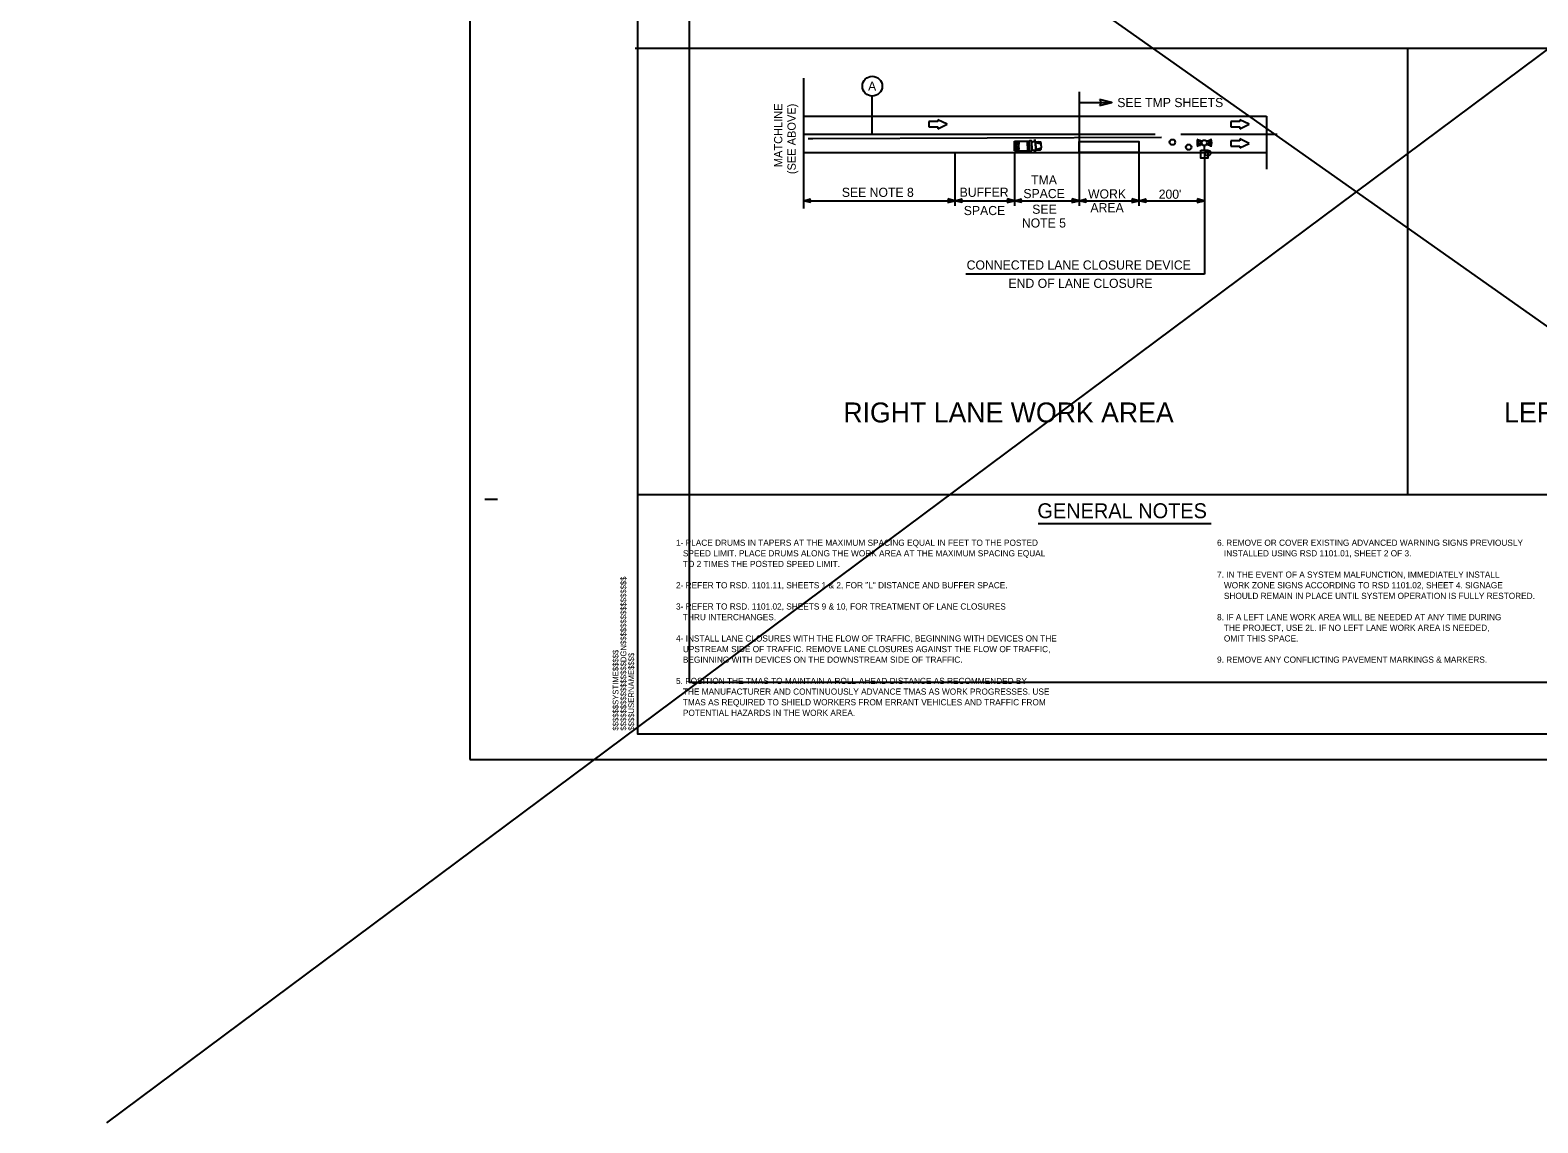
# Model space of a CAD drawing. Extents: x 1379436 to 1387057, y 792703 to 795604.
# Drawn here: x 1379436 to 1381631, y 792703 to 794294 of the extents above; entities that cross this region are included whole.
import ezdxf

# ---------------------------------------------------------------- set-up
doc = ezdxf.new("R2010")
doc.units = 0
for name, color, linetype in [('Default', 7, 'Continuous'), ('DEV BORDER CELL', 7, 'Continuous'), ('DEV DIRECTION OF TRAFFIC FLOW ARROW CELL', 7, 'Continuous'), ('DEV DRUM PLAN VIEW CELL', 7, 'Continuous'), ('DEV LINE TERMINATOR TYPE 3 CELL', 7, 'Continuous'), ('DEV TRUCK MOUNTED IMPACT ATTENUATOR CELL', 7, 'Continuous'), ('Drum Linestyle V8i', 7, 'Continuous'), ('Gray Area Fill Shapes', 7, 'Continuous'), ('Prop Mkg Skp Wht', 7, 'Continuous'), ('Prop Mkg Solid White Lane Line', 7, 'Continuous'), ('Prop Mkg Solid Yellow Edge Line', 7, 'Continuous'), ('Scratch_Level_0', 7, 'Continuous'), ('Sheet Plot Border Outside CELL', 7, 'Continuous'), ('Text', 7, 'Continuous')]:
    doc.layers.add(name, color=color, linetype=linetype)

msp = doc.modelspace()

# ---------------------------------------------------------------- linework, layer by layer
at = {"layer": 'Default'}
for p, q in [((1379547.9, 792703.3), (1383441.1, 795604.3)), ((1379436.3, 795421.7), (1382883.5, 792987.4)), ((1380317, 794267.8), (1382567, 794267.8)), ((1381442, 793618), (1381442, 794267.8)), ((1380662.3, 794142.3), (1380662.3, 794198)), ((1380963.2, 794204.2), (1380963.2, 794115.6)), ((1380320.7, 793618), (1381738.3, 793618))]:
    msp.add_line(p, q, dxfattribs=at)
msp.add_circle((1380662.3, 794212.4), 14.4, dxfattribs=at)
at = {"layer": 'DEV BORDER CELL'}
for p, q in [((1380098, 793611), (1380116.7, 793611)), ((1380320.7, 793269.7), (1380320.7, 793269.7))]:
    msp.add_line(p, q, dxfattribs=at)
msp.add_lwpolyline([(1382570.8, 794844.7), (1380320.7, 794844.7), (1380320.7, 793269.7), (1382570.8, 793269.7)], close=True, dxfattribs=at)
at = {"layer": 'DEV DIRECTION OF TRAFFIC FLOW ARROW CELL'}
for p, q in [((1380771.4, 794157), (1380757.6, 794163.5)), ((1380757.6, 794163.5), (1380757.6, 794160.9)), ((1381210.9, 794157), (1381197.2, 794163.5)), ((1381197.2, 794163.5), (1381197.2, 794160.9)), ((1380757.6, 794160.9), (1380744.8, 794160.9)), ((1380744.8, 794160.9), (1380744.8, 794153.2)), ((1380744.8, 794153.2), (1380757.6, 794153.2)), ((1380757.6, 794150.5), (1380771.4, 794157)), ((1380757.6, 794153.2), (1380757.6, 794150.5)), ((1381197.2, 794160.9), (1381184.4, 794160.9)), ((1381184.4, 794160.9), (1381184.4, 794153.2)), ((1381184.4, 794153.2), (1381197.2, 794153.2)), ((1381197.2, 794150.5), (1381210.9, 794157)), ((1381197.2, 794153.2), (1381197.2, 794150.5)), ((1381197.2, 794132.9), (1381184.4, 794132.9)), ((1381184.4, 794132.9), (1381184.4, 794125.2)), ((1381184.4, 794125.2), (1381197.2, 794125.2)), ((1381210.9, 794129.1), (1381197.2, 794135.5)), ((1381197.2, 794135.5), (1381197.2, 794132.9)), ((1381197.2, 794122.6), (1381210.9, 794129.1)), ((1381197.2, 794125.2), (1381197.2, 794122.6))]:
    msp.add_line(p, q, dxfattribs=at)
at = {"layer": 'DEV DRUM PLAN VIEW CELL'}
for centre in [(1381099.1, 794130.9), (1381099.1, 794130.9), (1381122.8, 794123.6), (1381122.8, 794123.6), (1381150.8, 794115.2), (1381150.8, 794115.2)]:
    msp.add_circle(centre, 4.08, dxfattribs=at)
at = {"layer": 'DEV LINE TERMINATOR TYPE 3 CELL'}
for points in [[(1380993.3, 794184.1), (1381011, 794188.6), (1380993.3, 794193)], [(1380993.3, 794184.1), (1381011, 794188.6), (1380993.3, 794193)], [(1380572.3, 794043), (1380561.9, 794045.6), (1380572.3, 794048.2)], [(1380572.3, 794043), (1380561.9, 794045.6), (1380572.3, 794048.2)], [(1380772.2, 794043), (1380782.6, 794045.6), (1380772.2, 794048.2)], [(1380772.2, 794043), (1380782.6, 794045.6), (1380772.2, 794048.2)], [(1380793, 794043), (1380782.6, 794045.6), (1380793, 794048.2)], [(1380793, 794043), (1380782.6, 794045.6), (1380793, 794048.2)], [(1380858.7, 794043), (1380869.1, 794045.6), (1380858.7, 794048.2)], [(1380858.7, 794043), (1380869.1, 794045.6), (1380858.7, 794048.2)], [(1380879.5, 794043), (1380869.1, 794045.6), (1380879.5, 794048.2)], [(1380879.5, 794043), (1380869.1, 794045.6), (1380879.5, 794048.2)], [(1380952.8, 794043), (1380963.2, 794045.6), (1380952.8, 794048.2)], [(1380952.8, 794043), (1380963.2, 794045.6), (1380952.8, 794048.2)], [(1380973.6, 794043), (1380963.2, 794045.6), (1380973.6, 794048.2)], [(1380973.6, 794043), (1380963.2, 794045.6), (1380973.6, 794048.2)], [(1381040.2, 794043), (1381050.5, 794045.6), (1381040.2, 794048.2)], [(1381040.2, 794043), (1381050.5, 794045.6), (1381040.2, 794048.2)], [(1381060.9, 794043), (1381050.5, 794045.6), (1381060.9, 794048.2)], [(1381060.9, 794043), (1381050.5, 794045.6), (1381060.9, 794048.2)], [(1381135.3, 794043), (1381145.6, 794045.6), (1381135.3, 794048.2)], [(1381135.3, 794043), (1381145.6, 794045.6), (1381135.3, 794048.2)]]:
    msp.add_lwpolyline(points, dxfattribs=at)
for centre, radius, start, end in [((1380989.4, 794188.6), 5.92, 311.3264, 48.6736), ((1380989.4, 794188.6), 5.92, 311.3264, 48.6736), ((1380574.6, 794045.6), 3.46, 131.3264, 228.6736), ((1380574.6, 794045.6), 3.46, 131.3264, 228.6736), ((1380769.9, 794045.6), 3.46, 311.3264, 48.6736), ((1380769.9, 794045.6), 3.46, 311.3264, 48.6736), ((1380795.2, 794045.6), 3.46, 131.3264, 228.6736), ((1380795.2, 794045.6), 3.46, 131.3264, 228.6736), ((1380856.5, 794045.6), 3.46, 311.3264, 48.6736), ((1380856.5, 794045.6), 3.46, 311.3264, 48.6736), ((1380881.8, 794045.6), 3.46, 131.3264, 228.6736), ((1380881.8, 794045.6), 3.46, 131.3264, 228.6736), ((1380950.5, 794045.6), 3.46, 311.3264, 48.6736), ((1380950.5, 794045.6), 3.46, 311.3264, 48.6736), ((1380975.8, 794045.6), 3.46, 131.3264, 228.6736), ((1380975.8, 794045.6), 3.46, 131.3264, 228.6736), ((1381037.9, 794045.6), 3.46, 311.3264, 48.6736), ((1381037.9, 794045.6), 3.46, 311.3264, 48.6736), ((1381063.2, 794045.6), 3.46, 131.3264, 228.6736), ((1381063.2, 794045.6), 3.46, 131.3264, 228.6736), ((1381133, 794045.6), 3.46, 311.3264, 48.6736), ((1381133, 794045.6), 3.46, 311.3264, 48.6736)]:
    msp.add_arc(centre, radius, start, end, dxfattribs=at)
at = {"layer": 'DEV TRUCK MOUNTED IMPACT ATTENUATOR CELL'}
for p, q in [((1380869.1, 794132.5), (1380891, 794132.5)), ((1380869.1, 794118.3), (1380869.1, 794132.5)), ((1380869.1, 794132.5), (1380869.1, 794129.8)), ((1380869.1, 794132.5), (1380869.1, 794129.8)), ((1380869.1, 794132.5), (1380869.1, 794129.8)), ((1380869.1, 794132.5), (1380869.1, 794129.8)), ((1380869.1, 794129.8), (1380869.1, 794132.5)), ((1380869.1, 794132.5), (1380871.5, 794132.5)), ((1380871.5, 794132.5), (1380869.1, 794129.8)), ((1380869.1, 794127.6), (1380873.5, 794132.5)), ((1380875.4, 794132.5), (1380869.1, 794125.4)), ((1380869.1, 794125.4), (1380869.1, 794127.6)), ((1380869.1, 794125.4), (1380875.4, 794118.3)), ((1380869.1, 794123.3), (1380869.1, 794125.4)), ((1380873.5, 794118.3), (1380869.1, 794123.3)), ((1380869.1, 794121), (1380869.1, 794118.3)), ((1380871.5, 794118.3), (1380869.1, 794121)), ((1380871.1, 794125.4), (1380875.4, 794130.3)), ((1380875.4, 794120.6), (1380871.1, 794125.4)), ((1380875.4, 794128.1), (1380873, 794125.4)), ((1380873.1, 794125.4), (1380875.4, 794122.8)), ((1380873.5, 794132.5), (1380875.4, 794132.5)), ((1380875.4, 794118.3), (1380875.4, 794132.5)), ((1380875.4, 794130.3), (1380875.4, 794128.1)), ((1380875.4, 794122.8), (1380875.4, 794120.6)), ((1380888, 794125.4), (1380888, 794132.5)), ((1380888, 794125.4), (1380888, 794118.3)), ((1380891, 794125.4), (1380891, 794132.5)), ((1380891, 794125.4), (1380891, 794118.3)), ((1380894.3, 794125.4), (1380894.3, 794132.5)), ((1380894.3, 794125.4), (1380894.3, 794118.3)), ((1380898.8, 794132.9), (1380898.8, 794134.6)), ((1380899.1, 794131.2), (1380899.1, 794134.6)), ((1380899.1, 794119.6), (1380899.1, 794116.2)), ((1380899.3, 794131.2), (1380899.3, 794134.6)), ((1380899.3, 794119.6), (1380899.3, 794116.2)), ((1380899.9, 794125.4), (1380899.9, 794130.5)), ((1380899.9, 794125.4), (1380899.9, 794120.3)), ((1380900.4, 794130.5), (1380908.1, 794128.4)), ((1380900.4, 794125.4), (1380900.4, 794130.5)), ((1380900.4, 794125.4), (1380900.4, 794120.3)), ((1380900.4, 794120.3), (1380908.1, 794122.4)), ((1380908.1, 794125.4), (1380908.1, 794128.4)), ((1380908.1, 794125.4), (1380908.1, 794122.4)), ((1380869.1, 794118.3), (1380891, 794118.3)), ((1380869.1, 794118.3), (1380871.5, 794118.3)), ((1380875.4, 794118.3), (1380873.5, 794118.3)), ((1380898.8, 794117.9), (1380898.8, 794116.2))]:
    msp.add_line(p, q, dxfattribs=at)
for centre in [(1380906.2, 794129.4), (1380906.2, 794121.4)]:
    msp.add_arc(centre, 2.12, 331.8801, 28.1199, dxfattribs=at)
for centre, major_axis, ratio, start_param, end_param in [((1380892.7, 794132.5), (1.67, 0), 0.269913, 0, 3.141593), ((1380897.1, 794130.1), (2.8, 0.35), 0.503092, 0, 3.141593), ((1380897.1, 794120.7), (2.8, -0.35), 0.503092, 3.141593, 6.283185), ((1380904.2, 794130.4), (3.82, -0.04), 0.2034, 0, 3.141593), ((1380904.2, 794120.4), (3.82, 0.04), 0.2034, 3.141593, 6.283185), ((1380892.7, 794118.3), (1.67, 0), 0.269913, 3.141593, 6.283185)]:
    msp.add_ellipse(centre, major_axis=major_axis, ratio=ratio, start_param=start_param, end_param=end_param, dxfattribs=at)
at = {"layer": 'Drum Linestyle V8i'}
msp.add_lwpolyline([(1380568.7, 794136.3), (1380575.9, 794136.3), (1381083.3, 794137.9)], dxfattribs=at)
at = {"layer": 'Gray Area Fill Shapes'}
msp.add_lwpolyline([(1380963.2, 794131.6), (1381050.5, 794131.6), (1381050.5, 794115.6), (1380963.2, 794115.6)], close=True, dxfattribs=at)
at = {"layer": 'Prop Mkg Skp Wht'}
msp.add_line((1381111.6, 794142.3), (1381251.6, 794142.3), dxfattribs=at)
at = {"layer": 'Prop Mkg Solid White Lane Line'}
for p, q in [((1380561.9, 794142.3), (1381073.8, 794142.3)), ((1380561.9, 794115.6), (1381236, 794115.6))]:
    msp.add_line(p, q, dxfattribs=at)
at = {"layer": 'Prop Mkg Solid Yellow Edge Line'}
msp.add_line((1380561.9, 794168.9), (1381236, 794168.9), dxfattribs=at)
at = {"layer": 'Scratch_Level_0'}
msp.add_line((1381236, 794168.9), (1381236, 794091.8), dxfattribs=at)
msp.add_lwpolyline([(1382495.8, 794769.7), (1380395.7, 794769.7), (1380395.7, 793344.7), (1381714, 793344.7), (1381714, 793522.1), (1382495.8, 793522.1)], close=True, dxfattribs=at)
at = {"layer": 'Sheet Plot Border Outside CELL'}
msp.add_lwpolyline([(1380076.3, 793232.2), (1382608.3, 793232.2), (1382608.3, 794882.2), (1380076.3, 794882.2)], close=True, dxfattribs=at)
at = {"layer": 'Text'}
for p, q in [((1380561.9, 794223.8), (1380561.9, 794034.5)), ((1380963.2, 794188.6), (1381011, 794188.6)), ((1381145.7, 794119.3), (1381145.7, 794125.9)), ((1380782.6, 794115.6), (1380782.6, 794038.1)), ((1380869.1, 794115.6), (1380869.1, 794038.1)), ((1380963.2, 794115.6), (1380963.2, 794038.1)), ((1381050.5, 794115.6), (1381050.5, 794038.1)), ((1381145.7, 794115.6), (1381145.7, 793938.7)), ((1380561.9, 794045.6), (1380782.6, 794045.6)), ((1380782.6, 794045.6), (1380869.1, 794045.6)), ((1380869.1, 794045.6), (1380963.2, 794045.6)), ((1380963.2, 794045.6), (1381050.5, 794045.6)), ((1381050.5, 794045.6), (1381145.7, 794045.6)), ((1381145.7, 793938.7), (1380798.3, 793938.7)), ((1380903.7, 793575.8), (1381155.4, 793575.8))]:
    msp.add_line(p, q, dxfattribs=at)
msp.add_lwpolyline([(1381140.6, 794119.3), (1381150.8, 794119.3), (1381150.8, 794107.8), (1381140.6, 794107.8)], close=True, dxfattribs=at)
msp.add_circle((1381145.7, 794129.9), 3.99, dxfattribs=at)
for centre, radius, start, end in [((1381152.7, 794129.9), 17.6, 161.0657, 198.9343), ((1381152.7, 794129.9), 15, 161.0657, 198.9343), ((1381152.7, 794129.9), 12.3, 161.0657, 198.9343), ((1381138.7, 794129.9), 12.3, 341.0657, 18.9343), ((1381138.7, 794129.9), 15, 341.0657, 18.9343), ((1381138.7, 794129.9), 17.6, 341.0657, 18.9343)]:
    msp.add_arc(centre, radius, start, end, dxfattribs=at)

# ---------------------------------------------------------------- texts
at = {"layer": 'Default'}
for s, p in [('MATCHLINE', (1380531.3, 794094.5)), ('(SEE ABOVE)', (1380550.8, 794084.3))]:
    msp.add_text(s, height=12, rotation=90, dxfattribs=at).set_placement(p)
for s, p in [('RIGHT LANE WORK AREA', (1380620.1, 793722.9)), ('LEFT LANE WORK AREA', (1381581.9, 793722.9))]:
    msp.add_text(s, height=29.027, dxfattribs=at).set_placement(p)
at = {"layer": 'DEV BORDER CELL'}
for s, p in [('$$$$$$$$$$$$$$$$DGN$$$$$$$$$$$$$$$$', (1380304.1, 793274.3)), ('$$$$$$SYSTIME$$$$$', (1380292.7, 793274.3)), ('$$$$USERNAME$$$$', (1380315.5, 793274.3))]:
    msp.add_text(s, height=8.376, rotation=90, dxfattribs=at).set_placement(p)
at = {"layer": 'Text'}
for s, height, p in [('A', 13.3, (1380656.1, 794205.7)), ('SEE TMP SHEETS', 13.304, (1381018.9, 794181.9)), ('TMA', 13.3, (1380893.5, 794069.3)), ('SEE NOTE 8', 13.3, (1380617.9, 794051.2)), ('BUFFER ', 13.31, (1380789.4, 794051.3)), ('SPACE', 13.3, (1380882.2, 794049.4)), ('WORK ', 13.3, (1380976.3, 794048.9)), ("200'", 13.3, (1381079.2, 794048.5)), ('SPACE', 13.31, (1380795.4, 794024.7)), ('SEE ', 13.3, (1380895.1, 794026.6)), ('AREA', 13.3, (1380979.8, 794028.9)), ('NOTE 5', 13.3, (1380880, 794006.6)), ('CONNECTED LANE CLOSURE DEVICE', 13.31, (1380799.6, 793945.4)), ('END OF LANE CLOSURE', 13.31, (1380860.5, 793918.8)), ('GENERAL NOTES', 21.707, (1380902.6, 793583.5)), ('1- PLACE DRUMS IN TAPERS AT THE MAXIMUM SPACING EQUAL IN FEET TO THE POSTED', 9, (1380376.5, 793543.3)), ('6. REMOVE OR COVER EXISTING ADVANCED WARNING SIGNS PREVIOUSLY', 9, (1381164.1, 793543.3)), ('   SPEED LIMIT. PLACE DRUMS ALONG THE WORK AREA AT THE MAXIMUM SPACING EQUAL', 9, (1380376.5, 793527.9)), ('   INSTALLED USING RSD 1101.01, SHEET 2 OF 3.', 9, (1381164.1, 793527.9)), ('   TO 2 TIMES THE POSTED SPEED LIMIT.', 9, (1380376.5, 793512.4)), ('7. IN THE EVENT OF A SYSTEM MALFUNCTION, IMMEDIATELY INSTALL', 9, (1381164.1, 793496.9)), ('2- REFER TO RSD. 1101.11, SHEETS 1 & 2, FOR "L" DISTANCE AND BUFFER SPACE.', 9, (1380376.5, 793481.4)), ('   WORK ZONE SIGNS ACCORDING TO RSD 1101.02, SHEET 4. SIGNAGE', 9, (1381164.1, 793481.4)), ('   SHOULD REMAIN IN PLACE UNTIL SYSTEM OPERATION IS FULLY RESTORED.', 9, (1381164.1, 793465.9)), ('3- REFER TO RSD. 1101.02, SHEETS 9 & 10, FOR TREATMENT OF LANE CLOSURES', 9, (1380376.5, 793450.5)), ('   THRU INTERCHANGES.', 9, (1380376.5, 793435)), ('8. IF A LEFT LANE WORK AREA WILL BE NEEDED AT ANY TIME DURING', 9, (1381164.1, 793435)), ('   THE PROJECT, USE 2L. IF NO LEFT LANE WORK AREA IS NEEDED,', 9, (1381164.1, 793419.5)), ('4- INSTALL LANE CLOSURES WITH THE FLOW OF TRAFFIC, BEGINNING WITH DEVICES ON THE ', 9, (1380376.5, 793404)), ('   UPSTREAM SIDE OF TRAFFIC. REMOVE LANE CLOSURES AGAINST THE FLOW OF TRAFFIC, ', 9, (1380376.5, 793388.5)), ('   OMIT THIS SPACE.', 9, (1381164.1, 793404)), ('   BEGINNING WITH DEVICES ON THE DOWNSTREAM SIDE OF TRAFFIC.', 9, (1380376.5, 793373.1)), ('9. REMOVE ANY CONFLICTING PAVEMENT MARKINGS & MARKERS.', 9, (1381164.1, 793373.1)), ('5. POSITION THE TMAS TO MAINTAIN A ROLL-AHEAD DISTANCE AS RECOMMENDED BY', 9, (1380376.5, 793342.1)), ('   THE MANUFACTURER AND CONTINUOUSLY ADVANCE TMAS AS WORK PROGRESSES. USE', 9, (1380376.5, 793326.6)), ('   TMAS AS REQUIRED TO SHIELD WORKERS FROM ERRANT VEHICLES AND TRAFFIC FROM', 9, (1380376.5, 793311.1)), ('   POTENTIAL HAZARDS IN THE WORK AREA.', 9, (1380376.5, 793295.7))]:
    msp.add_text(s, height=height, dxfattribs=at).set_placement(p)

doc.saveas('drawing.dxf')
